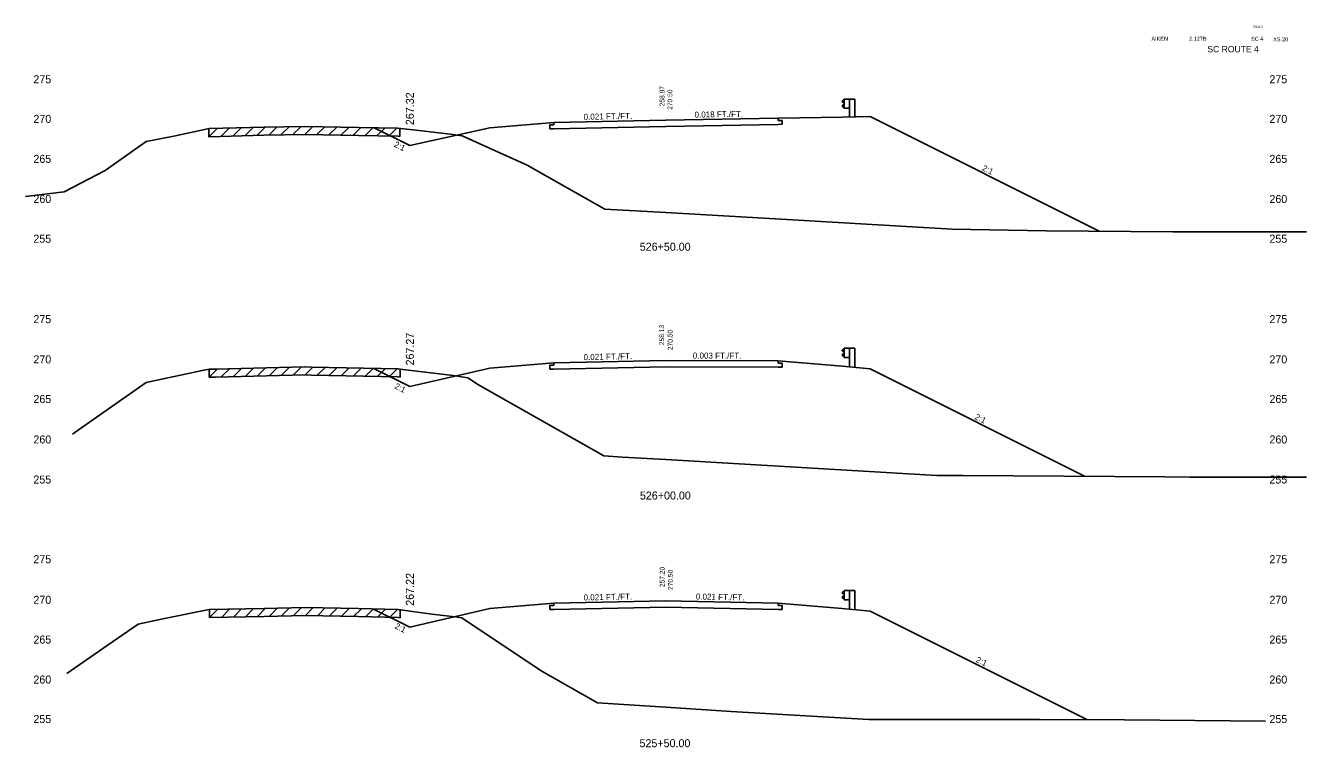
# Model space of a CAD drawing. Extents: x 883 to 1160, y 1002 to 4323.
# Drawn here: x 1000 to 1160, y 3197.2 to 3287.3 of the extents above; entities that cross this region are included whole.
import ezdxf

# ---------------------------------------------------------------- set-up
doc = ezdxf.new("R2010")
doc.units = 0
for name, color, linetype in [('Level 1', 7, 'Continuous'), ('Level 10', 7, 'Continuous'), ('Level 11', 7, 'Continuous'), ('Level 12', 7, 'Continuous'), ('Level 24', 7, 'Continuous'), ('Level 3', 7, 'Continuous'), ('Level 32', 7, 'Continuous'), ('Level 33', 7, 'Continuous'), ('Level 59', 7, 'Continuous'), ('Level 6', 7, 'Continuous'), ('Level 60', 7, 'Continuous'), ('Level 61', 7, 'Continuous'), ('Level 7', 7, 'Continuous')]:
    doc.layers.add(name, color=color, linetype=linetype)

msp = doc.modelspace()

# ---------------------------------------------------------------- linework, layer by layer
at = {"layer": 'Level 11'}
for p, q in [((1066, 3275.21), (1066, 3274.91)), ((1094, 3275.45), (1094, 3275.75)), ((1094.5, 3275.46), (1094, 3275.45)), ((1094.5, 3274.98), (1094.5, 3275.46)), ((1066, 3274.91), (1065.5, 3274.9)), ((1065.5, 3274.9), (1065.5, 3274.42)), ((1065.5, 3274.42), (1066, 3274.43)), ((1094, 3274.97), (1094.5, 3274.98)), ((1066, 3244.91), (1065.5, 3244.9)), ((1065.5, 3244.9), (1065.5, 3244.42)), ((1066, 3245.21), (1066, 3244.91)), ((1094, 3245.16), (1094, 3245.46)), ((1094.5, 3245.16), (1094, 3245.16)), ((1094.5, 3244.68), (1094.5, 3245.16)), ((1065.5, 3244.42), (1066, 3244.43)), ((1094, 3244.68), (1094.5, 3244.68)), ((1066, 3214.91), (1065.5, 3214.9)), ((1065.5, 3214.9), (1065.5, 3214.42)), ((1065.5, 3214.42), (1066, 3214.43)), ((1066, 3215.21), (1066, 3214.91)), ((1094, 3214.91), (1094, 3215.21)), ((1094.5, 3214.9), (1094, 3214.91)), ((1094, 3214.43), (1094.5, 3214.42)), ((1094.5, 3214.42), (1094.5, 3214.9))]:
    msp.add_line(p, q, dxfattribs=at)
at = {"layer": 'Level 12'}
for p, q in [((1080, 3274.72), (1066, 3274.43)), ((1094, 3274.97), (1080, 3274.72)), ((1080, 3244.72), (1066, 3244.43)), ((1094, 3244.68), (1080, 3244.72)), ((1080, 3214.72), (1066, 3214.43)), ((1094, 3214.43), (1080, 3214.72))]:
    msp.add_line(p, q, dxfattribs=at)
at = {"layer": 'Level 24'}
for p, q in [((1102.27, 3278.07), (1102, 3277.87)), ((1102, 3277.87), (1102, 3277.82)), ((1102, 3277.82), (1102.27, 3277.62)), ((1102, 3277.3), (1102.27, 3277.5)), ((1102, 3277.25), (1102, 3277.3)), ((1102.27, 3277.05), (1102, 3277.25)), ((1102.27, 3276.98), (1102.27, 3278.14)), ((1102.27, 3278.14), (1102.94, 3278.14)), ((1102.27, 3276.98), (1102.94, 3276.98)), ((1102.94, 3278.14), (1102.94, 3275.91)), ((1102.94, 3278.14), (1103.6, 3278.14)), ((1103.6, 3278.14), (1103.6, 3275.92)), ((1102.27, 3246.97), (1102, 3246.77)), ((1102, 3246.77), (1102, 3246.72)), ((1102, 3246.72), (1102.27, 3246.52)), ((1102.27, 3245.87), (1102.27, 3247.04)), ((1102.27, 3247.04), (1102.94, 3247.04)), ((1102.94, 3247.04), (1102.94, 3244.7)), ((1102.94, 3247.04), (1103.6, 3247.04)), ((1103.6, 3247.04), (1103.6, 3244.63)), ((1102, 3246.2), (1102.27, 3246.4)), ((1102, 3246.15), (1102, 3246.2)), ((1102.27, 3245.95), (1102, 3246.15)), ((1102.27, 3245.87), (1102.94, 3245.87)), ((1102.27, 3216.72), (1102, 3216.52)), ((1102, 3216.52), (1102, 3216.47)), ((1102, 3216.47), (1102.27, 3216.27)), ((1102, 3215.95), (1102.27, 3216.15)), ((1102.27, 3215.63), (1102.27, 3216.79)), ((1102.27, 3216.79), (1102.94, 3216.79)), ((1102.94, 3216.79), (1102.94, 3214.45)), ((1102.94, 3216.79), (1103.6, 3216.79)), ((1103.6, 3216.79), (1103.6, 3214.38)), ((1102, 3215.9), (1102, 3215.95)), ((1102.27, 3215.7), (1102, 3215.9)), ((1102.27, 3215.63), (1102.94, 3215.63))]:
    msp.add_line(p, q, dxfattribs=at)
at = {"layer": 'Level 59'}
for p, q in [((1066, 3275.21), (1080, 3275.5)), ((1080, 3275.5), (1094, 3275.75)), ((1066, 3245.21), (1080, 3245.5)), ((1080, 3245.5), (1094, 3245.46)), ((1066, 3215.21), (1080, 3215.5)), ((1080, 3215.5), (1094, 3215.21))]:
    msp.add_line(p, q, dxfattribs=at)
at = {"layer": 'Level 6'}
for p, q in [((1058, 3274.54), (1066, 3275.21)), ((1094, 3275.75), (1102, 3275.89)), ((1102, 3275.89), (1105.5, 3275.96)), ((1058, 3244.54), (1066, 3245.21)), ((1094, 3245.46), (1102, 3244.79)), ((1102, 3244.79), (1105.5, 3244.44)), ((1058, 3214.54), (1066, 3215.21)), ((1094, 3215.21), (1102, 3214.54)), ((1102, 3214.54), (1105.5, 3214.19))]:
    msp.add_line(p, q, dxfattribs=at)
at = {"layer": 'Level 60'}
for p, q in [((1018.52, 3273.51), (1022.92, 3274.44)), ((1022.92, 3274.44), (1029.75, 3274.61)), ((1029.75, 3274.61), (1034.9, 3274.73)), ((1034.9, 3274.73), (1041.6, 3274.58)), ((1041.6, 3274.58), (1046.5, 3274.5)), ((1046.5, 3274.5), (1049.48, 3274.16)), ((1049.48, 3274.16), (1053.37, 3273.7)), ((1053.37, 3273.7), (1054.52, 3273.53)), ((1009.93, 3269.23), (1015.08, 3272.84)), ((1015.08, 3272.84), (1018.52, 3273.51)), ((1054.52, 3273.53), (1062.67, 3269.87)), ((1004.81, 3266.54), (1009.93, 3269.23)), ((1062.67, 3269.87), (1072.36, 3264.4)), ((1000, 3265.99), (1004.81, 3266.54)), ((1072.36, 3264.4), (1080, 3263.97)), ((1080, 3263.97), (1091.5, 3263.32)), ((1091.5, 3263.32), (1115.77, 3261.9)), ((1115.77, 3261.9), (1127.49, 3261.69)), ((1127.49, 3261.69), (1143.33, 3261.57)), ((1143.33, 3261.57), (1154.78, 3261.57)), ((1154.78, 3261.57), (1160, 3261.57)), ((1015.07, 3242.76), (1022.25, 3244.27)), ((1022.25, 3244.27), (1022.91, 3244.4)), ((1022.91, 3244.4), (1023.74, 3244.42)), ((1023.74, 3244.42), (1034.89, 3244.7)), ((1034.89, 3244.7), (1035.71, 3244.68)), ((1035.71, 3244.68), (1046.56, 3244.44)), ((1046.56, 3244.44), (1047.11, 3244.36)), ((1047.11, 3244.36), (1053.4, 3243.62)), ((1053.4, 3243.62), (1055.25, 3243.34)), ((1055.25, 3243.34), (1056.57, 3242.46)), ((1006.75, 3236.93), (1015.07, 3242.76)), ((1056.57, 3242.46), (1072.24, 3233.6)), ((1005.84, 3236.3), (1006.75, 3236.93)), ((1072.24, 3233.6), (1074.55, 3233.45)), ((1074.55, 3233.45), (1080, 3233.13)), ((1080, 3233.13), (1113.82, 3231.15)), ((1113.82, 3231.15), (1117.08, 3231.16)), ((1117.08, 3231.16), (1142.36, 3230.97)), ((1142.36, 3230.97), (1145.43, 3230.95)), ((1145.43, 3230.95), (1160, 3230.95)), ((1022.93, 3214.4), (1029.79, 3214.55)), ((1029.79, 3214.55), (1034.94, 3214.68)), ((1034.94, 3214.68), (1041.54, 3214.52)), ((1041.54, 3214.52), (1046.56, 3214.41)), ((1046.56, 3214.41), (1050.76, 3213.82)), ((1014.04, 3212.6), (1017.36, 3213.3)), ((1017.36, 3213.3), (1022.93, 3214.4)), ((1050.76, 3213.82), (1053.65, 3213.48)), ((1053.65, 3213.48), (1054.49, 3213.36)), ((1054.49, 3213.36), (1064.39, 3206.76)), ((1010.19, 3209.91), (1014.04, 3212.6)), ((1005.16, 3206.43), (1010.19, 3209.91)), ((1064.39, 3206.76), (1071.45, 3202.76)), ((1071.45, 3202.76), (1080, 3202.2)), ((1080, 3202.2), (1088.15, 3201.66)), ((1088.15, 3201.66), (1105.32, 3200.66)), ((1105.32, 3200.66), (1126.68, 3200.7)), ((1126.68, 3200.7), (1137.28, 3200.62)), ((1137.28, 3200.62), (1154.91, 3200.49))]:
    msp.add_line(p, q, dxfattribs=at)
at = {"layer": 'Level 61'}
for p, q in [((1023.92, 3274.46), (1022.89, 3273.43)), ((1022.89, 3274.43), (1022.89, 3273.43)), ((1022.92, 3273.44), (1029.75, 3273.61)), ((1025.42, 3274.5), (1024.39, 3273.48)), ((1026.92, 3274.54), (1025.89, 3273.51)), ((1028.42, 3274.58), (1027.39, 3273.55)), ((1029.92, 3274.61), (1028.89, 3273.59)), ((1029.75, 3273.61), (1034.9, 3273.73)), ((1031.41, 3274.65), (1030.39, 3273.62)), ((1032.91, 3274.68), (1031.89, 3273.66)), ((1034.41, 3274.71), (1033.39, 3273.69)), ((1035.87, 3274.7), (1034.89, 3273.73)), ((1034.9, 3273.73), (1041.6, 3273.58)), ((1037.37, 3274.67), (1036.39, 3273.69)), ((1038.87, 3274.64), (1037.89, 3273.66)), ((1040.37, 3274.6), (1039.39, 3273.63)), ((1041.87, 3274.57), (1040.89, 3273.59)), ((1043.38, 3274.55), (1042.39, 3273.56)), ((1044.88, 3274.52), (1043.89, 3273.54)), ((1046.38, 3274.5), (1045.39, 3273.51)), ((1046.74, 3273.47), (1046.74, 3274.47)), ((1022.89, 3273.43), (1022.92, 3273.44)), ((1041.6, 3273.58), (1046.5, 3273.5)), ((1046.5, 3273.5), (1046.74, 3273.47)), ((1023.95, 3244.42), (1022.93, 3243.4)), ((1022.93, 3244.4), (1022.93, 3243.4)), ((1022.93, 3243.4), (1023.74, 3243.42)), ((1023.74, 3243.42), (1034.89, 3243.7)), ((1025.45, 3244.46), (1024.43, 3243.44)), ((1026.95, 3244.5), (1025.93, 3243.47)), ((1028.45, 3244.54), (1027.43, 3243.51)), ((1029.95, 3244.57), (1028.93, 3243.55)), ((1031.45, 3244.61), (1030.43, 3243.59)), ((1032.95, 3244.65), (1031.93, 3243.62)), ((1034.45, 3244.69), (1033.43, 3243.66)), ((1034.89, 3243.7), (1035.71, 3243.68)), ((1035.9, 3244.67), (1034.93, 3243.7)), ((1035.71, 3243.68), (1046.56, 3243.44)), ((1037.41, 3244.64), (1036.43, 3243.66)), ((1038.91, 3244.61), (1037.93, 3243.63)), ((1040.41, 3244.57), (1039.43, 3243.59)), ((1041.91, 3244.54), (1040.93, 3243.56)), ((1043.41, 3244.51), (1042.43, 3243.53)), ((1044.91, 3244.47), (1043.93, 3243.49)), ((1046.41, 3244.44), (1045.43, 3243.46)), ((1046.56, 3243.44), (1046.77, 3243.41)), ((1046.77, 3243.41), (1046.77, 3244.41)), ((1023.98, 3214.42), (1022.96, 3213.4)), ((1022.96, 3214.4), (1022.96, 3213.4)), ((1025.48, 3214.46), (1024.46, 3213.43)), ((1026.98, 3214.49), (1025.96, 3213.47)), ((1028.48, 3214.52), (1027.46, 3213.5)), ((1029.98, 3214.56), (1028.96, 3213.54)), ((1031.48, 3214.6), (1030.46, 3213.57)), ((1032.98, 3214.63), (1031.96, 3213.61)), ((1034.48, 3214.67), (1033.46, 3213.65)), ((1035.93, 3214.66), (1034.96, 3213.68)), ((1037.43, 3214.62), (1036.46, 3213.64)), ((1038.93, 3214.58), (1037.96, 3213.61)), ((1040.43, 3214.55), (1039.46, 3213.57)), ((1041.94, 3214.51), (1040.96, 3213.53)), ((1043.44, 3214.48), (1042.46, 3213.5)), ((1044.94, 3214.44), (1043.96, 3213.46)), ((1046.44, 3214.41), (1045.46, 3213.43)), ((1022.96, 3213.4), (1029.79, 3213.55)), ((1029.79, 3213.55), (1034.94, 3213.68)), ((1034.94, 3213.68), (1041.54, 3213.52)), ((1041.54, 3213.52), (1046.56, 3213.41)), ((1046.56, 3213.41), (1046.81, 3213.37)), ((1046.81, 3213.37), (1046.81, 3214.37))]:
    msp.add_line(p, q, dxfattribs=at)
at = {"layer": 'Level 7'}
for p, q in [((1105.5, 3275.96), (1134.13, 3261.64)), ((1043.54, 3274.54), (1048, 3272.32)), ((1048, 3272.32), (1058, 3274.54)), ((1043.52, 3244.5), (1048, 3242.27)), ((1048, 3242.27), (1058, 3244.54)), ((1105.5, 3244.44), (1132.29, 3231.05)), ((1043.48, 3214.47), (1048, 3212.22)), ((1048, 3212.22), (1058, 3214.54)), ((1105.5, 3214.19), (1132.57, 3200.66))]:
    msp.add_line(p, q, dxfattribs=at)

# ---------------------------------------------------------------- texts
at = {"layer": 'Level 1'}
for s, height, p in [('AIKEN', 0.5, (1140.64, 3285.41)), (' 2.127B', 0.5, (1145.15, 3285.41)), ('SC 4', 0.5, (1153.09, 3285.41)), ('XS 20', 0.5, (1155.85, 3285.35)), ('SC ROUTE 4', 0.8, (1147.63, 3283.97)), ('526+50.00', 1, (1076.72, 3259.2)), ('526+00.00', 1, (1076.74, 3228.14)), ('525+50.00', 1, (1076.69, 3197.22))]:
    msp.add_text(s, height=height, dxfattribs=at).set_placement(p)
at = {"layer": 'Level 10'}
for s, p in [('258.97', (1079.81, 3277.23)), ('258.13', (1079.76, 3247.41)), ('257.20', (1079.82, 3217.21))]:
    msp.add_text(s, height=0.6, rotation=90, dxfattribs=at).set_placement(p)
at = {"layer": 'Level 3'}
for s, height, p in [('ROAD', 0.3, (1153.38, 3287)), (' 275', 1, (1000.6, 3280.11)), (' 275', 1, (1155.01, 3280.11)), (' 270', 1, (1000.6, 3275.16)), (' 270', 1, (1155.01, 3275.16)), (' 265', 1, (1000.6, 3270.17)), (' 265', 1, (1155.01, 3270.17)), (' 260', 1, (1000.6, 3265.16)), (' 260', 1, (1155.01, 3265.16)), (' 255', 1, (1000.6, 3260.2)), (' 255', 1, (1155.01, 3260.2)), (' 275', 1, (1000.6, 3250.16)), (' 275', 1, (1155.01, 3250.16)), (' 270', 1, (1000.6, 3245.14)), (' 270', 1, (1155.01, 3245.14)), (' 265', 1, (1000.6, 3240.19)), (' 265', 1, (1155.01, 3240.19)), (' 260', 1, (1000.6, 3235.14)), (' 260', 1, (1155.01, 3235.14)), (' 255', 1, (1000.6, 3230.14)), (' 255', 1, (1155.01, 3230.14)), (' 275', 1, (1000.6, 3220.19)), (' 275', 1, (1155.01, 3220.19)), (' 270', 1, (1000.6, 3215.12)), (' 270', 1, (1155.01, 3215.12)), (' 265', 1, (1000.6, 3210.16)), (' 265', 1, (1155.01, 3210.16)), (' 260', 1, (1000.6, 3205.17)), (' 260', 1, (1155.01, 3205.17)), (' 255', 1, (1000.6, 3200.24)), (' 255', 1, (1155.01, 3200.24))]:
    msp.add_text(s, height=height, dxfattribs=at).set_placement(p)
at = {"layer": 'Level 32'}
for s, rotation, p in [('0.021 FT./FT.', 1.1916, (1069.71, 3275.54)), ('0.018 FT./FT.', 1.0229, (1083.57, 3275.81)), ('2:1', 333.435, (1045.95, 3272.23)), ('2:1', 333.435, (1119.42, 3269.28)), ('0.021 FT./FT.', 1.1916, (1069.71, 3245.54)), ('0.003 FT./FT.', 359.8303, (1083.35, 3245.74)), ('2:1', 333.435, (1046.01, 3242.05)), ('2:1', 333.435, (1118.5, 3238.22)), ('0.021 FT./FT.', 1.1916, (1069.71, 3215.54)), ('0.021 FT./FT.', 358.8084, (1083.72, 3215.67)), ('2:1', 333.435, (1046.04, 3212.1)), ('2:1', 333.435, (1118.64, 3207.9))]:
    msp.add_text(s, height=0.75, rotation=rotation, dxfattribs=at).set_placement(p)
at = {"layer": 'Level 33'}
for s, p in [('267.32', (1048.5, 3274.88)), ('267.27', (1048.5, 3244.88)), ('267.22', (1048.5, 3214.88))]:
    msp.add_text(s, height=1, rotation=90, dxfattribs=at).set_placement(p)
at = {"layer": 'Level 59'}
for p in [(1080.79, 3276.56), (1080.82, 3246.56), (1080.85, 3216.62)]:
    msp.add_text(' 270.50', height=0.6, rotation=90, dxfattribs=at).set_placement(p)

doc.saveas('drawing.dxf')
